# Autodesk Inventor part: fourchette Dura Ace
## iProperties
Created: 2011-11
Part Number: fourchette Dura Ace
Document SubType Name: Modeling
Designer: Laur
Density: 1 g/cm^3
Mass: 0.683838 g
Surface Area: 14.7242 cm^2
Volume: 0.683838 cm^3
Author: Laur
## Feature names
1. Extrusion1
2. Extrusion2
3. Extrusion3
4. Extrusion4
5. Extrusion5
6. Extrusion6
7. Extrusion7
